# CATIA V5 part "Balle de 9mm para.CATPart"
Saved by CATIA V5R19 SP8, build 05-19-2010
Part number: Balle de 9mm parabellum
Bounding box of the stored display mesh (mm): x -4.514 to 4.514, y 0 to 15, z -4.514 to 4.514
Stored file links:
  C:\Users\Arthur\Desktop\Catia parts\GLOCK\Balle de 9mm para.CATPart
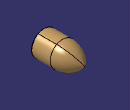
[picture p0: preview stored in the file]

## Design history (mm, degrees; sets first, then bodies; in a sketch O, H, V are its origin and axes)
Set1
  Sketch1 on yz-plane, origin (0, 0, 0), H (0, 1, 0), V (0, 0, 1)
    line L1 (0, 0) -> (0, 4.515)
    line L2 (0, 4.515) -> (7, 4.515)
    point P2 (7, 4.515)
    construction line L3 (-24.2574, 0) -> (15, 0)
    point P4 (15, 0)
    arc A1 centre (7, -4.83) radius 9.345 from (15, 0) to (7, 4.515) ccw
    point P6 (15, 0)
    construction line L4 (7, 15.6995) -> (7, -14.3005)
    distance P4 L4 = 8
    distance L2 L3 = 4.515
    distance L4 L1 = 7
    vertical: L1 V, L4 V
    horizontal: L2 H, L3 H
    coincidence: L3 H, P6 H, P6 P4, L4 P2
    tangency: A1 L2
Body1 (main body)
  Shaft1: profile Sketch1, axis Sketch1.H, angle 360
  Sketch2 on face of Shaft1 from Sketch1.L1, origin (0, 0, 0), H (1, 0, 0), V (0, 0, 1)
    circle A1 centre (0, 0) radius 3
    radius A1 = 3
  Pocket1: profile Sketch2, direction (0, 1, 0), length 3
  Chamfer1: length 0.3, angle 45, on edge [face of Shaft1 from Sketch1.L1 | face of Pocket1 from Sketch2.A1]; edge [face of Shaft1 from Sketch1.L1 | face of Shaft1 from Sketch1.L2]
